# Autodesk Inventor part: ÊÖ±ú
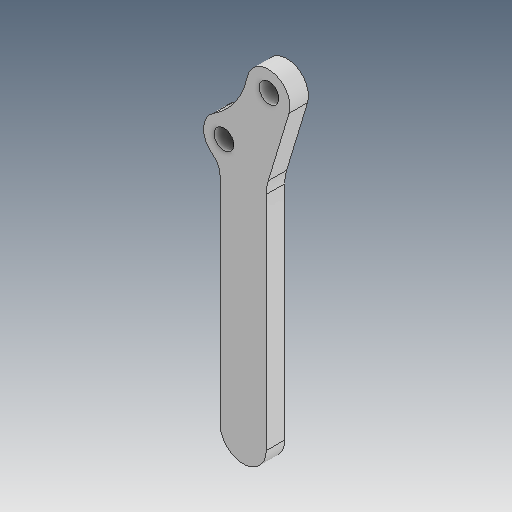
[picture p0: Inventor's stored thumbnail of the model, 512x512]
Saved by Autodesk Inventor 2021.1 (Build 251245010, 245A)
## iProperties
Created: 2020-03
Part Number: ÊÖ±ú
Material: Ogólny
Document SubType Name: Modeling
Designer: user
Density: 1 g/cm^3
Appearance: Domyślna
Author: user
Revision Number: ÈÎºÎ
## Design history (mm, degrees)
feature "Í¹Ì¨-À­Éì1"
node "Bryła1"
